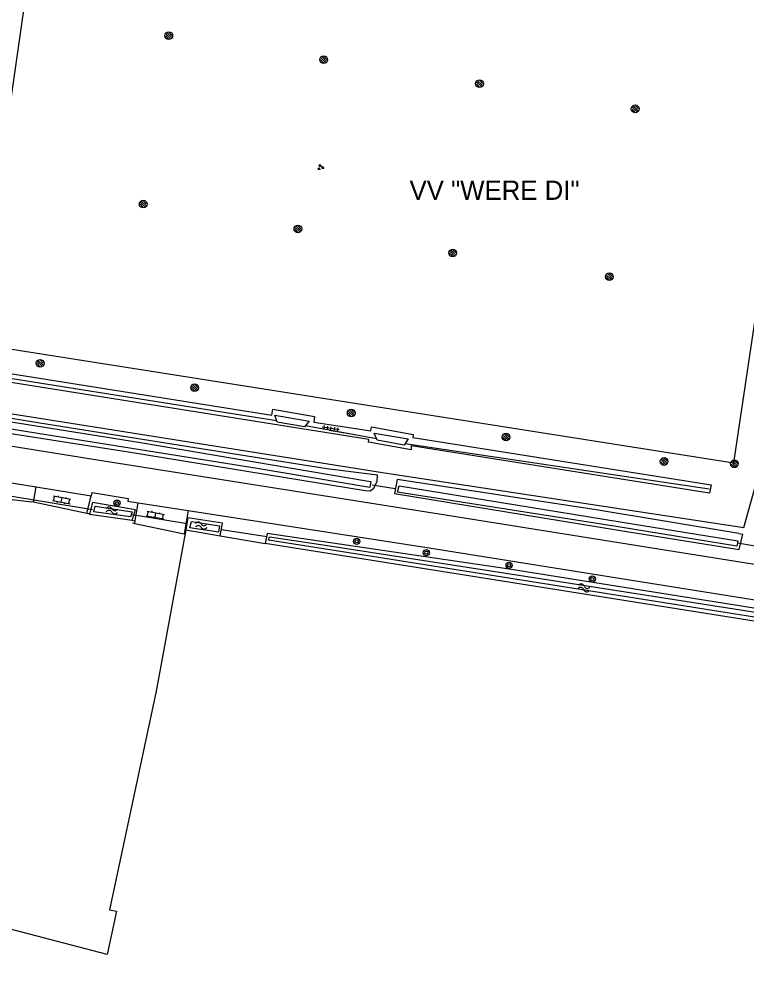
# Model space of a CAD drawing. Extents: x 135999 to 138000, y 396000 to 398501.
# Drawn here: x 136374.9 to 136469.3, y 396283.9 to 396408.9 of the extents above; entities that cross this region are included whole.
import ezdxf

# ---------------------------------------------------------------- set-up
doc = ezdxf.new("R2010")
doc.units = 0
for name, color, linetype in [('bs-afsc-belijning', 7, 'Continuous'), ('bs-afsc-hekwerk laag', 7, 'Continuous'), ('bs-afsc-poort', 7, 'Continuous'), ('bs-symb-cornervlag', 7, 'Continuous'), ('bs-symb-sproeier', 7, 'Continuous'), ('gg-afsc-hekwerk', 7, 'Continuous'), ('gg-afsc-lijn draadraster', 7, 'Continuous'), ('gg-bbg-overig bouwwerk', 7, 'Continuous'), ('gg-knt-verharding', 7, 'Continuous'), ('gg-kntw-bovenkant insteek waterloop', 7, 'Continuous'), ('gg-kntw-waterlijn', 7, 'Continuous'), ('gg-kwrk-duiker nz buis', 7, 'Continuous'), ('gt-anno-naam bijzondere bebouwing', 7, 'Continuous'), ('gt-grn-groengrens', 7, 'Continuous'), ('gt-symb-boom', 7, 'Continuous'), ('gt-symb-groenvak', 7, 'Continuous'), ('gt-symb-klinker verharding', 7, 'Continuous'), ('gt-symb-tegel verharding', 7, 'Continuous'), ('gt-symb-watersymbool', 7, 'Continuous'), ('gx-grn-maaiveld', 7, 'Continuous')]:
    doc.layers.add(name, color=color, linetype=linetype)

# ---------------------------------------------------------------- blocks, each defined once
blk = doc.blocks.new('gt0-WA')
at = {"layer": 'gt-symb-watersymbool'}
for centre, start, end in [((-0.32, 0.02), 28.0725, 151.9275), ((0.43, 0.42), 208.0725, 331.9275), ((-0.32, -0.43), 28.0725, 151.9275), ((0.43, -0.03), 208.0725, 331.9275)]:
    blk.add_arc(centre, 0.425, start, end, dxfattribs=at)
blk = doc.blocks.new('gt0-BOOM')
at = {"layer": 'gt-symb-boom'}
for radius in [0.4, 0.2]:
    blk.add_circle((0, 0), radius, dxfattribs=at)
blk = doc.blocks.new('bs0-SPROEIER')
at = {"layer": 'bs-symb-sproeier'}
for p, q in [((-0.34, 0.2), (0.2, -0.34)), ((-0.21, 0.35), (0.34, -0.2)), ((0.03, 0.4), (0.4, 0.03)), ((-0.4, -0.03), (-0.03, -0.4))]:
    blk.add_line(p, q, dxfattribs=at)
blk.add_circle((0, 0), 0.5, dxfattribs=at)
blk = doc.blocks.new('gt0-GRVAK')
at = {"layer": 'gt-symb-groenvak'}
for p, q in [((-0.11, 0.19), (-0.23, 0.24)), ((-0.18, 0.15), (0.09, 0.15)), ((-0.09, 0.21), (-0.16, 0.32)), ((-0.05, 0.21), (-0.05, 0.39)), ((0, 0.21), (0.06, 0.32)), ((0.02, 0.19), (0.13, 0.24)), ((0.26, -0.05), (0.2, 0.06)), ((0.3, -0.05), (0.3, 0.13)), ((0.35, -0.05), (0.41, 0.06)), ((-0.24, -0.23), (-0.36, -0.18)), ((-0.32, -0.26), (-0.05, -0.26)), ((-0.23, -0.21), (-0.29, -0.1)), ((-0.18, -0.2), (-0.18, -0.02)), ((-0.14, -0.21), (-0.07, -0.1)), ((-0.12, -0.23), (0, -0.18)), ((0.24, -0.07), (0.12, -0.02)), ((0.17, -0.11), (0.44, -0.11)), ((0.37, -0.07), (0.49, -0.02))]:
    blk.add_line(p, q, dxfattribs=at)
blk = doc.blocks.new('gt0-TEG1')
at = {"layer": 'gt-symb-tegel verharding'}
for p, q in [((-1.12, 0), (1.13, 0)), ((-0.9, -0.25), (-0.9, 0.25)), ((-0.45, -0.25), (-0.45, 0.25)), ((0, -0.25), (0, 0.25)), ((0.45, -0.25), (0.45, 0.25)), ((0.9, -0.25), (0.9, 0.25))]:
    blk.add_line(p, q, dxfattribs=at)
blk = doc.blocks.new('bs0-CORNVLG')
at = {"layer": 'bs-symb-cornervlag'}
for p, q in [((-0.34, 0.2), (0.2, -0.34)), ((-0.21, 0.35), (0.34, -0.2)), ((0.03, 0.4), (0.4, 0.03)), ((-0.4, -0.03), (-0.03, -0.4))]:
    blk.add_line(p, q, dxfattribs=at)
blk.add_circle((0, 0), 0.5, dxfattribs=at)
blk = doc.blocks.new('gt0-KL1')
at = {"layer": 'gt-symb-klinker verharding'}
for p, q in [((-1.15, 0.3), (1.15, 0.3)), ((-1, -0.3), (-1, 0.3)), ((-0.5, 0.3), (-0.5, 0.45)), ((0, -0.3), (0, 0.3)), ((0.5, 0.3), (0.5, 0.45)), ((1, -0.3), (1, 0.3)), ((-1.15, -0.3), (1.15, -0.3)), ((-0.5, -0.45), (-0.5, -0.3)), ((0.5, -0.45), (0.5, -0.3))]:
    blk.add_line(p, q, dxfattribs=at)

msp = doc.modelspace()

# ---------------------------------------------------------------- linework, layer by layer
at = {"layer": 'bs-afsc-belijning'}
msp.add_lwpolyline([(136378.4, 396430.68), (136369.25, 396366.81), (136467.63, 396351.32), (136477.19, 396415.48), (136378.4, 396430.68)], dxfattribs=at)
at = {"layer": 'bs-afsc-hekwerk laag'}
for p, q in [((136368.96, 396363.04), (136408.3, 396356.82)), ((136412.06, 396356.17), (136421.25, 396354.49)), ((136424.98, 396353.83), (136464.43, 396347.96))]:
    msp.add_line(p, q, dxfattribs=at)
at = {"layer": 'bs-afsc-poort'}
msp.add_line((136422.05, 396350.08), (136423.15, 396349.87), dxfattribs=at)
at = {"layer": 'gg-afsc-hekwerk'}
for p, q in [((136368.96, 396363.04), (136408.3, 396356.82)), ((136363.66, 396359.3), (136422.05, 396350.08)), ((136412.06, 396356.17), (136421.25, 396354.49)), ((136415.12, 396355.55), (136418.22, 396355.04)), ((136424.98, 396353.83), (136464.43, 396347.96)), ((136422.05, 396350.08), (136423.15, 396349.87)), ((136376.74, 396346.21), (136376.49, 396346.26)), ((136376.74, 396346.21), (136376.49, 396346.26)), ((136383.67, 396344.74), (136376.74, 396346.21)), ((136383.67, 396344.74), (136376.74, 396346.21)), ((136383.93, 396344.68), (136383.67, 396344.74)), ((136383.93, 396344.68), (136383.67, 396344.74)), ((136389.9, 396343.42), (136389.64, 396343.47)), ((136396.32, 396342.07), (136389.9, 396343.42)), ((136396.32, 396342.07), (136389.9, 396343.42))]:
    msp.add_line(p, q, dxfattribs=at)
msp.add_lwpolyline([(136423.15, 396349.87), (136468.92, 396342.92), (136476.19, 396368.89)], dxfattribs=at)
at = {"layer": 'gg-afsc-lijn draadraster'}
msp.add_lwpolyline([(136396.54, 396342.6), (136392.66, 396321.69), (136386.63, 396293.33), (136387.51, 396293.15), (136386.31, 396287.51), (136371.58, 396291.38), (136369.37, 396283.98), (136356.27, 396287.68)], dxfattribs=at)
at = {"layer": 'gg-bbg-overig bouwwerk'}
for points in [[(136408.05, 396357.51), (136412.51, 396356.73), (136411.9, 396355.97), (136408.38, 396356.58), (136408.05, 396357.51)], [(136424.84, 396353.62), (136421.34, 396354.25), (136420.98, 396355.18), (136425.38, 396354.43), (136424.84, 396353.62)]]:
    msp.add_lwpolyline(points, dxfattribs=at)
at = {"layer": 'gg-knt-verharding'}
for p, q in [((136373.06, 396348.85), (136377.11, 396348.19)), ((136376.74, 396346.21), (136377.11, 396348.19)), ((136377.11, 396348.19), (136384.25, 396347.03)), ((136383.67, 396344.74), (136384.25, 396347.03)), ((136389.96, 396343.79), (136390.35, 396346.13)), ((136390.35, 396346.13), (136396.81, 396345.13)), ((136396.81, 396345.13), (136396.4, 396342.62)), ((136389.9, 396343.42), (136389.96, 396343.79)), ((136396.4, 396342.62), (136396.32, 396342.07))]:
    msp.add_line(p, q, dxfattribs=at)
for points in [[(136368.61, 396362.54), (136368.78, 396363.67), (136407.69, 396357.51), (136407.82, 396358.3), (136413.21, 396357.34), (136413.12, 396356.6), (136420.54, 396355.48), (136420.61, 396355.98), (136426.03, 396355), (136425.97, 396354.62), (136464.69, 396348.47), (136464.49, 396347.39), (136425.77, 396353.51), (136425.75, 396353.01), (136420.24, 396353.98), (136420.29, 396354.34), (136368.61, 396362.54)], [(136350.8, 396357.21), (136385.34, 396351.65), (136429.38, 396344.68), (136470.07, 396338.2), (136496.3, 396334.06), (136506.47, 396332.41)], [(136384.25, 396347.03), (136384.28, 396347.03), (136384.37, 396347.45), (136389.05, 396346.7), (136388.99, 396346.34), (136390.35, 396346.13)], [(136396.81, 396345.13), (136428.1, 396340.29), (136469.84, 396333.61), (136495.1, 396329.5), (136505.31, 396327.98)]]:
    msp.add_lwpolyline(points, dxfattribs=at)
at = {"layer": 'gg-kntw-bovenkant insteek waterloop'}
for p, q in [((136384.03, 396344.66), (136389.56, 396343.87)), ((136396.54, 396342.6), (136400.99, 396341.85)), ((136468.27, 396342.14), (136468.79, 396342.06))]:
    msp.add_line(p, q, dxfattribs=at)
for points in [[(136354.29, 396360.25), (136353.51, 396360.16), (136352.86, 396359.7), (136352.52, 396358.59), (136366.03, 396356.33), (136389.35, 396352.71), (136419.78, 396347.74), (136420.45, 396347.69), (136420.93, 396348.01), (136421.37, 396348.95), (136421.38, 396349.72), (136414.83, 396350.55), (136377.59, 396356.48), (136356.72, 396359.9), (136354.29, 396360.25)], [(136468.27, 396342.14), (136449.75, 396345.23), (136423.95, 396349.15), (136423.6, 396347.33), (136452.67, 396342.58), (136468.32, 396340.09), (136468.79, 396342.06)], [(136389.56, 396343.87), (136390.01, 396345.23), (136384.4, 396346.18), (136384.03, 396344.66)], [(136400.99, 396341.85), (136401.28, 396343.49), (136396.8, 396344.17), (136396.54, 396342.6)], [(136515.75, 396325.29), (136497, 396327.9), (136470.23, 396332.46), (136438.49, 396337.5), (136407.08, 396342.16), (136406.82, 396340.84)], [(136517.54, 396322.65), (136514.5, 396322.99), (136496.76, 396326.42), (136480.62, 396329.13), (136406.82, 396340.84)]]:
    msp.add_lwpolyline(points, dxfattribs=at)
at = {"layer": 'gg-kntw-waterlijn'}
for points in [[(136354.15, 396359.75), (136369.73, 396357.27), (136390.37, 396353.99), (136419.96, 396348.99), (136420.54, 396348.89), (136420.4, 396348.1), (136405.8, 396350.57), (136376.23, 396355.31), (136353.83, 396358.91), (136354.15, 396359.75)], [(136424.21, 396348.35), (136454.5, 396343.41), (136468.14, 396341.18), (136468.03, 396340.51), (136452.36, 396343.06), (136423.99, 396347.52), (136424.21, 396348.35)], [(136384.77, 396345.71), (136389.56, 396344.97), (136389.33, 396344.3), (136384.6, 396344.95), (136384.77, 396345.71)], [(136397.24, 396343.72), (136400.9, 396343.16), (136400.77, 396342.31), (136397.06, 396342.88), (136397.24, 396343.72)], [(136518.11, 396322.6), (136517.98, 396323.09), (136514.97, 396323.68), (136505.14, 396325.61), (136498.36, 396326.66), (136473.85, 396330.73), (136423.17, 396338.76), (136407.26, 396341.28), (136407.37, 396341.73)], [(136407.37, 396341.73), (136414.9, 396340.6), (136443.64, 396336.12), (136481.23, 396330.26), (136513.46, 396325), (136517.67, 396324.32), (136520.39, 396323.87), (136521.59, 396324.2), (136526.54, 396326.83), (136528.54, 396327.67), (136528.8, 396327.06), (136526.55, 396326.11), (136521.15, 396323.28), (136520.12, 396322.42)]]:
    msp.add_lwpolyline(points, dxfattribs=at)
at = {"layer": 'gg-kwrk-duiker nz buis'}
for p, q in [((136423.68, 396347.93), (136420.72, 396348.43)), ((136384.4, 396345.21), (136372.63, 396347.15)), ((136396.68, 396343.42), (136389.58, 396344.58)), ((136407.02, 396341.72), (136401.14, 396342.6)), ((136473.82, 396339.89), (136468.1, 396340.9))]:
    msp.add_line(p, q, dxfattribs=at)
at = {"layer": 'gt-grn-groengrens'}
for p, q in [((136372.55, 396346.74), (136376.49, 396346.26)), ((136383.93, 396344.68), (136384.03, 396344.66)), ((136389.56, 396343.87), (136389.96, 396343.79)), ((136396.4, 396342.62), (136396.54, 396342.6)), ((136400.99, 396341.85), (136406.82, 396340.84))]:
    msp.add_line(p, q, dxfattribs=at)
at = {"layer": 'gx-grn-maaiveld'}
msp.add_lwpolyline([(136396.54, 396342.6), (136392.66, 396321.69), (136386.63, 396293.33), (136387.51, 396293.15), (136386.31, 396287.51), (136371.58, 396291.38), (136369.37, 396283.98), (136369.26, 396279.36), (136362.18, 396281.35), (136358.74, 396278.83), (136346.32, 396282.1), (136348.08, 396290)], dxfattribs=at)

# ---------------------------------------------------------------- block references
at = {"layer": 'bs-symb-cornervlag'}
msp.add_blockref('bs0-CORNVLG', (136467.71, 396351.19), dxfattribs=at)
at = {"layer": 'bs-symb-sproeier'}
for p in [(136394.31, 396406.75), (136414.41, 396403.63), (136434.63, 396400.51), (136454.83, 396397.25), (136390.99, 396384.89), (136411.06, 396381.67), (136431.15, 396378.53), (136451.47, 396375.48), (136377.62, 396364.22), (136397.66, 396361.07), (136417.98, 396357.78), (136438.07, 396354.68), (136458.58, 396351.49)]:
    msp.add_blockref('bs0-SPROEIER', p, dxfattribs=at)
at = {"layer": 'gt-symb-boom'}
for p in [(136387.59, 396346.09), (136418.69, 396341.12), (136427.74, 396339.65), (136438.47, 396338.01), (136449.27, 396336.25)]:
    msp.add_blockref('gt0-BOOM', p, dxfattribs=at)
at = {"layer": 'gt-symb-groenvak'}
msp.add_blockref('gt0-GRVAK', (136414, 396389.66), dxfattribs=at)
at = {"layer": 'gt-symb-klinker verharding', "rotation": -10.54573436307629}
for p in [(136380.42, 396346.52), (136392.58, 396344.54)]:
    msp.add_blockref('gt0-KL1', p, dxfattribs=at)
at = {"layer": 'gt-symb-tegel verharding', "rotation": 171.1405706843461}
msp.add_blockref('gt0-TEG1', (136415.31, 396355.76), dxfattribs=at)
at = {"layer": 'gt-symb-watersymbool'}
for p in [(136386.87, 396345.14), (136398.45, 396343.18)]:
    msp.add_blockref('gt0-WA', p, dxfattribs=at)
at = {"layer": 'gt-symb-watersymbool', "rotation": -8.972626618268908}
msp.add_blockref('gt0-WA', (136448.13, 396335.1), dxfattribs=at)

# ---------------------------------------------------------------- texts
at = {"layer": 'gt-anno-naam bijzondere bebouwing'}
msp.add_text('VV "WERE DI"', height=2.5, dxfattribs=at).set_placement((136425.55, 396385.44))

doc.saveas('drawing.dxf')
